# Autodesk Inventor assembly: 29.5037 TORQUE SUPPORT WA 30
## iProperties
Created: 2007-07
Part Number: 29.5037 TORQUE SUPPORT WA 30
Document SubType Name: Assembly
Designer: Andy Moles
Author: Andy Moles
